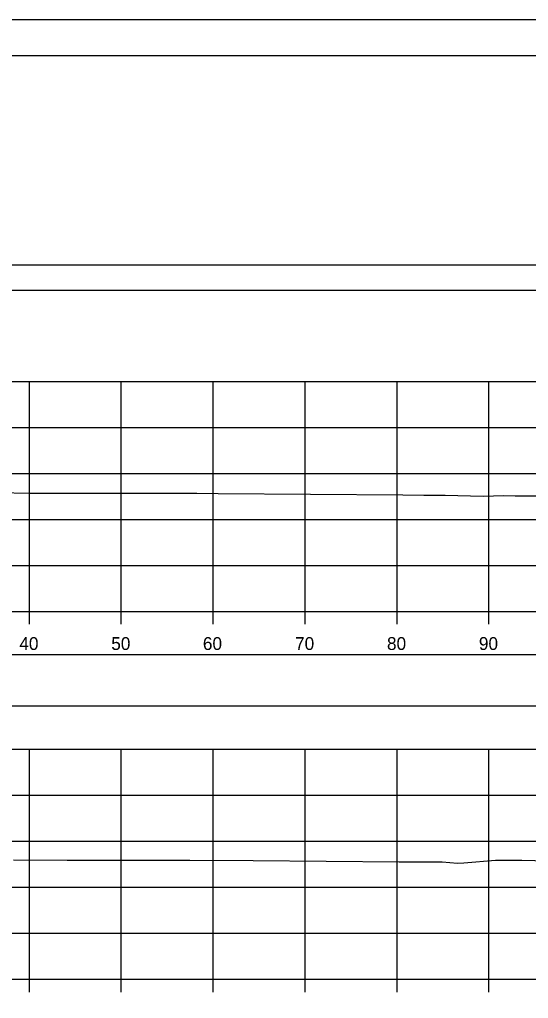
# Model space of a CAD drawing. Extents: x 1369627 to 1374022, y 380035 to 398173.
# Drawn here: x 1370218.2 to 1370273.5, y 382061.8 to 382168.3 of the extents above; entities that cross this region are included whole.
import ezdxf

# ---------------------------------------------------------------- set-up
doc = ezdxf.new("R2010")
doc.units = 0
for name, color, linetype in [('Default', 7, 'Continuous'), ('R_Axis', 7, 'Continuous'), ('R_Axis Annot', 7, 'Continuous'), ('R_Border', 7, 'Continuous'), ('R_Exist Surface', 7, 'Continuous'), ('R_Grid', 7, 'Continuous'), ('R_No Plot', 7, 'Continuous')]:
    doc.layers.add(name, color=color, linetype=linetype)

msp = doc.modelspace()

# ---------------------------------------------------------------- linework, layer by layer
at = {"layer": 'Default'}
for points in [[(1370029.24, 382138.84), (1370329.24, 382138.84), (1370329.24, 382141.54), (1370029.24, 382141.54)], [(1370029.24, 382093.64), (1370329.24, 382093.64), (1370329.24, 382099.16), (1370029.24, 382099.16)]]:
    msp.add_lwpolyline(points, close=True, dxfattribs=at)
at = {"layer": 'R_Axis'}
for p, q in [((1370029.24, 382103.9), (1370329.24, 382103.9)), ((1370219.24, 382102.5), (1370219.24, 382103.9)), ((1370229.24, 382102.5), (1370229.24, 382103.9)), ((1370239.24, 382102.5), (1370239.24, 382103.9)), ((1370249.24, 382102.5), (1370249.24, 382103.9)), ((1370259.24, 382102.5), (1370259.24, 382103.9)), ((1370269.24, 382102.5), (1370269.24, 382103.9)), ((1370029.24, 382063.9), (1370329.24, 382063.9)), ((1370219.24, 382062.5), (1370219.24, 382063.9)), ((1370229.24, 382062.5), (1370229.24, 382063.9)), ((1370239.24, 382062.5), (1370239.24, 382063.9)), ((1370249.24, 382062.5), (1370249.24, 382063.9)), ((1370259.24, 382062.5), (1370259.24, 382063.9)), ((1370269.24, 382062.5), (1370269.24, 382063.9))]:
    msp.add_line(p, q, dxfattribs=at)
at = {"layer": 'R_Border'}
msp.add_line((1370021.24, 382164.36), (1370337.42, 382164.36), dxfattribs=at)
at = {"layer": 'R_Exist Surface'}
for points in [[(1370215.89, 382116.84), (1370219.23, 382116.76), (1370222.56, 382116.74), (1370237.45, 382116.75), (1370239.8, 382116.73), (1370259.88, 382116.56), (1370262.15, 382116.55), (1370264.47, 382116.53), (1370268.63, 382116.44), (1370270.88, 382116.49), (1370270.88, 382116.49), (1370272.09, 382116.47), (1370276.4, 382116.46)], [(1370217.52, 382076.88), (1370223.37, 382076.84), (1370236.71, 382076.85), (1370243.59, 382076.8), (1370259.46, 382076.67), (1370263.53, 382076.67), (1370264.16, 382076.65), (1370265.83, 382076.51), (1370266.51, 382076.56), (1370269.95, 382076.84), (1370271.87, 382076.84), (1370272.4, 382076.85), (1370272.82, 382076.85), (1370275.66, 382076.78)]]:
    msp.add_lwpolyline(points, dxfattribs=at)
at = {"layer": 'R_Grid'}
for p, q in [((1370029.24, 382128.9), (1370329.24, 382128.9)), ((1370219.24, 382103.9), (1370219.24, 382128.9)), ((1370229.24, 382103.9), (1370229.24, 382128.9)), ((1370239.24, 382103.9), (1370239.24, 382128.9)), ((1370249.24, 382103.9), (1370249.24, 382128.9)), ((1370259.24, 382103.9), (1370259.24, 382128.9)), ((1370269.24, 382103.9), (1370269.24, 382128.9)), ((1370029.24, 382123.9), (1370329.24, 382123.9)), ((1370029.24, 382118.9), (1370329.24, 382118.9)), ((1370029.24, 382113.9), (1370329.24, 382113.9)), ((1370029.24, 382108.9), (1370329.24, 382108.9)), ((1370029.24, 382103.9), (1370329.24, 382103.9)), ((1370029.24, 382088.9), (1370329.24, 382088.9)), ((1370219.24, 382063.9), (1370219.24, 382088.9)), ((1370229.24, 382063.9), (1370229.24, 382088.9)), ((1370239.24, 382063.9), (1370239.24, 382088.9)), ((1370249.24, 382063.9), (1370249.24, 382088.9)), ((1370259.24, 382063.9), (1370259.24, 382088.9)), ((1370269.24, 382063.9), (1370269.24, 382088.9)), ((1370029.24, 382083.9), (1370329.24, 382083.9)), ((1370029.24, 382078.9), (1370329.24, 382078.9)), ((1370029.24, 382073.9), (1370329.24, 382073.9)), ((1370029.24, 382068.9), (1370329.24, 382068.9)), ((1370029.24, 382063.9), (1370329.24, 382063.9))]:
    msp.add_line(p, q, dxfattribs=at)
at = {"layer": 'R_No Plot'}
msp.add_line((1370008.84, 382168.25), (1370342.17, 382168.25), dxfattribs=at)
for points in [[(1370008.83, 382168.25), (1370342.17, 382168.25), (1370342.17, 381954.92), (1370008.83, 381954.92)], [(1370255.16, 382164.36), (1370274.78, 382164.36), (1370274.78, 382154.48), (1370290.89, 382154.48), (1370314.09, 382154.48), (1370314.09, 382121.81), (1370337.3, 382121.81), (1370337.42, 381958.9), (1370021.24, 381958.9), (1370021.24, 382164.36)]]:
    msp.add_lwpolyline(points, close=True, dxfattribs=at)

# ---------------------------------------------------------------- texts
at = {"layer": 'R_Axis Annot'}
for s, p in [('40', (1370218.15, 382099.7)), ('50', (1370228.15, 382099.7)), ('60', (1370238.12, 382099.7)), ('70', (1370248.15, 382099.7)), ('80', (1370258.15, 382099.7)), ('90', (1370268.15, 382099.7))]:
    msp.add_text(s, height=1.4, dxfattribs=at).set_placement(p)

doc.saveas('drawing.dxf')
